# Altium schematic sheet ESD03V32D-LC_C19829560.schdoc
size 127 x 101 mm
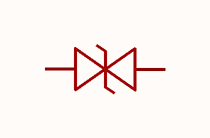
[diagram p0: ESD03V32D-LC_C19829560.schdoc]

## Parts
U?  esd03v32d-lc_c19829560  [SOD-323_L1.7-W1.3-LS2.5-BI]  (value not drawn)

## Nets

Not connected (* = marked no-connect by the designer): U? 1(K) 2(A)

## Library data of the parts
U? = esd03v32d-lc_c19829560: 极性:双向;反向截止电压(Vrwm):3.3V;最大钳位电压:16V;峰值脉冲功率(Ppp):250W;击穿电压:4V;; Manufacturer: TECH PUBLIC(台舟); AddInBom: yes; ModelId: 3c4d3117213c44d8be2b8463c3660d20; ModelTransform: 98.425,51.181,0,0,0,0,-0.001,0.006,0; polarity: 双向; Reverse Stand-Off Voltage (Vrwm): 3.3V; Maximum Clamping Voltage: 16V; Peak Pulse Power Dissipation (Ppp): 250W; Breakdown Voltage: 4V; Reverse Leakage Current (Ir): 200nA; Number of Lines: 单路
